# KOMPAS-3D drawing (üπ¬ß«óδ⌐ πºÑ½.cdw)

Referenced files in C:\Documents and Settings\GooDMaN\Мои документы\Мои работы для шараги\Работы для помощников\Ремонт буксового узла (букс и поводков)\: Буксовый узел.frw, Буксовый узел.cdw
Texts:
  ВСТАВЬ СВОЙ ШИФР
  Буксовый узел
  Домашний пк
  Текст на чертеже
  Размерные надписи
  Шероховатость
  Линия-выноска #1
  Линия-выноска #2
  Линия-выноска #3
  Отклонения формы и база
  Заголовок таблицы
  Ячейка таблицы
  Стрелка вида
  Обозначение изменения
  Фигурная скобка
  Номер узла
  Марка координационной оси
  VRCB
  Выносная надпись
  Обозначение узла
  Марка/позиционное обозначение с линией-выноской
  Марка/позиционное обозначение на линии
  Марка/позиционное обозначение без линии-выноски
  GooDMaN
  Слой 1
  Иванов
  ПЭР.30.4.00.00.30.ВО-
Dimensions and other numbers on the sheet: 7; 1; 2; 3; 4; 5; 6; 8; 0; 9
